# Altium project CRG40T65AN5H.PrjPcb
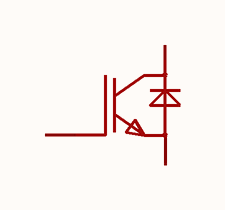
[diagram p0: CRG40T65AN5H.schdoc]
1 sheet, 1 parts. Net scope: global (net labels, ports and power ports of the same name join across sheets).

## Sheet CRG40T65AN5H.schdoc
size 127 x 101 mm

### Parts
U?  crg40t65an5h  [TO-3PN_L15.8-W5.0-P5.45-L]  (value not drawn)

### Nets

Not connected (* = marked no-connect by the designer): U? 1(G) 2(C) 3(E)

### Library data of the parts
U? = crg40t65an5h: IGBT类型:FS(场截止);耗散功率(Pd):250W;集射极击穿电压(Vces):650V;集电极电流(Ic):40A;; Manufacturer: CRMICRO(华润微); AddInBom: yes; ModelId: 55613033c80c42c790e40c0b8fde0471; ModelTransform: 622.046,189.3697,0,0,0,0,0,11.811,-196.85; Pd - Power Dissipation: 250W; Collector-Emitter Breakdown Voltage (Vces): 650V; Current - Collector(Ic): 40A; Current - Collector Pulsed (Icm): 160A; Vce Saturation(VCE(sat)): 1.65V; Gate-Emitter Threshold Voltage (Vge(th)@Ic): 3.5V@0.25mA; Gate Charge(Qg): 97nC@15V; Input Capacitance(Cies): 2.805nF; Output Capacitance(Coes): 119pF; Reverse Transfer Capacitance (Cres): 17pF; Td(on): 54ns; Td(off): 200ns; Turn-On Energy (Eon): 1.8mJ; Switching Energy(Eoff): 720uJ; Reverse Recovery Time(trr): 60ns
